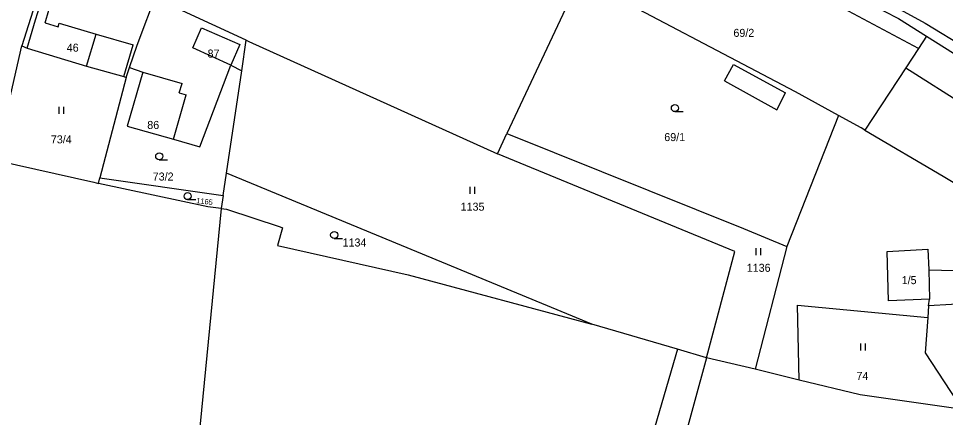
# Model space of a CAD drawing. Extents: x -746176 to -739709, y -1128407 to -1124482.
# Drawn here: x -742573.8 to -742377, y -1126067.4 to -1125982.8 of the extents above; entities that cross this region are included whole.
import ezdxf

# ---------------------------------------------------------------- set-up
doc = ezdxf.new("R2010")
doc.units = 0
for name, color, linetype in [('Vrstva 33', 7, 'Continuous'), ('Vrstva 42', 7, 'Continuous'), ('Vrstva 44', 7, 'Continuous'), ('Vrstva 47', 7, 'Continuous')]:
    doc.layers.add(name, color=color, linetype=linetype)

msp = doc.modelspace()

# ---------------------------------------------------------------- linework, layer by layer
at = {"layer": 'Vrstva 33'}
for p, q in [((-742567.25, -1125970.2), (-742573.08, -1125988.58)), ((-742454.6, -1125974.2), (-742470.09, -1126007.17)), ((-742380.97, -1125986.53), (-742382.69, -1125989.14)), ((-742576.14, -1126001.93), (-742573.08, -1125988.58)), ((-742526.38, -1125993.88), (-742525.42, -1125987.39)), ((-742550.91, -1125995.29), (-742550.22, -1125993.2)), ((-742529.61, -1126015.62), (-742526.38, -1125993.88)), ((-742550.91, -1125995.29), (-742556.49, -1126016.56)), ((-742399.65, -1126003.37), (-742410.68, -1126031.18)), ((-742472.11, -1126011.47), (-742470.09, -1126007.17)), ((-742556.81, -1126017.77), (-742556.49, -1126016.56)), ((-742556.49, -1126016.56), (-742530.31, -1126020.34)), ((-742530.31, -1126020.34), (-742529.61, -1126015.62)), ((-742452.02, -1126047.65), (-742529.61, -1126015.62)), ((-742530.31, -1126020.34), (-742530.79, -1126023.12)), ((-742410.68, -1126031.18), (-742417.35, -1126057.17)), ((-742433.87, -1126052.94), (-742452.02, -1126047.65)), ((-742427.68, -1126054.77), (-742433.87, -1126052.94)), ((-742417.35, -1126057.17), (-742427.68, -1126054.77)), ((-742408.01, -1126059.51), (-742417.35, -1126057.17))]:
    msp.add_line(p, q, dxfattribs=at)
for points in [[(-742444.75, -1125953.11), (-742386.93, -1125982.77), (-742380.97, -1125986.53)], [(-742382.69, -1125989.14), (-742398.6, -1125980.67), (-742445.94, -1125955.65)], [(-742399.65, -1126003.37), (-742408.8, -1125998.36), (-742454.6, -1125974.2)], [(-742550.22, -1125993.2), (-742548.63, -1125988.42), (-742544.26, -1125976.88)], [(-742525.42, -1125987.39), (-742539.86, -1125980.7), (-742539.1, -1125978.71)], [(-742528.71, -1125992.67), (-742536.8, -1125989.01), (-742534.92, -1125984.73), (-742526.82, -1125988.31), (-742528.71, -1125992.67)], [(-742380.97, -1125986.53), (-742365.73, -1125996.13), (-742363.63, -1125997.63), (-742356.74, -1126002.55), (-742344.5, -1126013.38)], [(-742573.08, -1125988.58), (-742571.93, -1125989.09), (-742559.35, -1125992.89), (-742551.46, -1125995.07), (-742550.91, -1125995.29)], [(-742525.42, -1125987.39), (-742524.92, -1125987.63), (-742472.11, -1126011.47)], [(-742382.69, -1125989.14), (-742385.4, -1125993.25), (-742394.08, -1126006.45)], [(-742550.22, -1125993.2), (-742547.37, -1125994.19), (-742550.69, -1126005.62), (-742540.91, -1126008.42), (-742535.29, -1126010.02), (-742528.71, -1125992.67), (-742526.38, -1125993.88)], [(-742394.08, -1126006.45), (-742394.87, -1126005.98), (-742399.65, -1126003.37)], [(-742394.08, -1126006.45), (-742377.42, -1126016.26), (-742373.55, -1126018.6), (-742347.83, -1126023.87), (-742347.76, -1126023.57)], [(-742470.09, -1126007.17), (-742419.86, -1126027.33), (-742410.68, -1126031.18)], [(-742578.37, -1126012.89), (-742557.79, -1126017.55), (-742556.81, -1126017.77)], [(-742427.68, -1126054.77), (-742421.67, -1126032.23), (-742472.11, -1126011.47)], [(-742530.79, -1126023.12), (-742533.62, -1126022.77), (-742556.81, -1126017.77)], [(-742530.79, -1126023.12), (-742541.03, -1126128.32), (-742551.09, -1126231.6), (-742645.51, -1126221.02)], [(-742530.79, -1126023.12), (-742529.6, -1126023.26), (-742518.21, -1126026.98), (-742517.74, -1126027.24), (-742518.78, -1126030.97), (-742491.05, -1126037.15), (-742452.02, -1126047.65)], [(-742389.08, -1126042.73), (-742389.31, -1126032.23), (-742380.68, -1126031.76), (-742380.48, -1126036.11), (-742380.34, -1126042.38), (-742389.08, -1126042.73)], [(-742408.01, -1126059.51), (-742408.36, -1126043.59), (-742380.73, -1126046.24)], [(-742370.32, -1126042.62), (-742370.8, -1126043.17), (-742380.56, -1126043.75), (-742380.73, -1126046.24)], [(-742380.73, -1126046.24), (-742381.25, -1126053.76), (-742374.55, -1126064.02)], [(-742433.87, -1126052.94), (-742447.8, -1126100.68), (-742456.41, -1126109.29), (-742463.16, -1126192.21), (-742472.54, -1126297.27), (-742476.24, -1126360.79), (-742482.39, -1126414.71)], [(-742427.68, -1126054.77), (-742440.74, -1126102.42), (-742430.76, -1126104.41), (-742424.03, -1126105.75), (-742421.29, -1126105.88)], [(-742374.74, -1126065.53), (-742395.07, -1126062.68), (-742408.01, -1126059.51)]]:
    msp.add_lwpolyline(points, dxfattribs=at)
at = {"layer": 'Vrstva 44'}
for p, q in [((-742565.19, -1126003.03), (-742565.19, -1126001.53)), ((-742564.19, -1126003.03), (-742564.19, -1126001.53)), ((-742434.42, -1126002.55), (-742432.67, -1126002.55)), ((-742543.91, -1126012.77), (-742542.16, -1126012.77)), ((-742477.91, -1126020.02), (-742477.91, -1126018.52)), ((-742476.91, -1126020.02), (-742476.91, -1126018.52)), ((-742537.89, -1126021.22), (-742536.14, -1126021.22)), ((-742506.76, -1126029.47), (-742505.01, -1126029.47)), ((-742417.16, -1126032.99), (-742417.16, -1126031.49)), ((-742416.16, -1126032.99), (-742416.16, -1126031.49)), ((-742394.93, -1126053.24), (-742394.93, -1126051.74)), ((-742393.93, -1126053.24), (-742393.93, -1126051.74))]:
    msp.add_line(p, q, dxfattribs=at)
for centre in [(-742434.42, -1126001.8), (-742543.91, -1126012.02), (-742537.89, -1126020.47), (-742506.76, -1126028.72)]:
    msp.add_circle(centre, 0.75, dxfattribs=at)
at = {"layer": 'Vrstva 47'}
for p, q in [((-742396.61, -1125975.35), (-742381.3, -1125983.74)), ((-742570.16, -1125983.03), (-742568.42, -1125977.34)), ((-742568.14, -1125983.67), (-742566.48, -1125977.96)), ((-742571.93, -1125989.09), (-742570.16, -1125983.03)), ((-742568.14, -1125983.67), (-742565.4, -1125984.52)), ((-742565.4, -1125984.52), (-742565.18, -1125983.78)), ((-742565.18, -1125983.78), (-742557.33, -1125986.12)), ((-742381.3, -1125983.74), (-742366, -1125993.07)), ((-742559.35, -1125992.89), (-742557.33, -1125986.12)), ((-742557.33, -1125986.12), (-742549.43, -1125988.35)), ((-742551.46, -1125995.07), (-742549.43, -1125988.35)), ((-742423.91, -1125996.04), (-742421.99, -1125992.51)), ((-742421.99, -1125992.51), (-742410.9, -1125998.54)), ((-742385.4, -1125993.25), (-742369.01, -1126003.63)), ((-742547.37, -1125994.19), (-742539.06, -1125996.58)), ((-742539.69, -1125998.58), (-742539.06, -1125996.58)), ((-742423.91, -1125996.04), (-742412.8, -1126002.17)), ((-742540.91, -1126008.42), (-742538.2, -1125999.01)), ((-742539.69, -1125998.58), (-742538.2, -1125999.01)), ((-742412.8, -1126002.17), (-742410.9, -1125998.54)), ((-742380.48, -1126036.11), (-742368.99, -1126036.39)), ((-742380.56, -1126043.75), (-742380.34, -1126042.38))]:
    msp.add_line(p, q, dxfattribs=at)

# ---------------------------------------------------------------- texts
at = {"layer": 'Vrstva 42'}
for s, p in [('69/2', (-742421.99, -1125986.68)), ('46', (-742563.55, -1125989.82)), ('87', (-742533.65, -1125991.07)), ('86', (-742546.45, -1126006.22)), ('69/1', (-742436.67, -1126008.8)), ('73/4', (-742566.92, -1126009.28)), ('73/2', (-742545.29, -1126017.17)), ('1135', (-742479.91, -1126023.57)), ('1134', (-742504.98, -1126031.17)), ('1136', (-742419.16, -1126036.54)), ('1/5', (-742386.26, -1126039.16)), ('74', (-742395.86, -1126059.49))]:
    msp.add_text(s, height=1.7, dxfattribs=at).set_placement(p)
msp.add_text('1165', height=1.14, rotation=353, dxfattribs=at).set_placement((-742536.09, -1126021.95))

doc.saveas('drawing.dxf')
